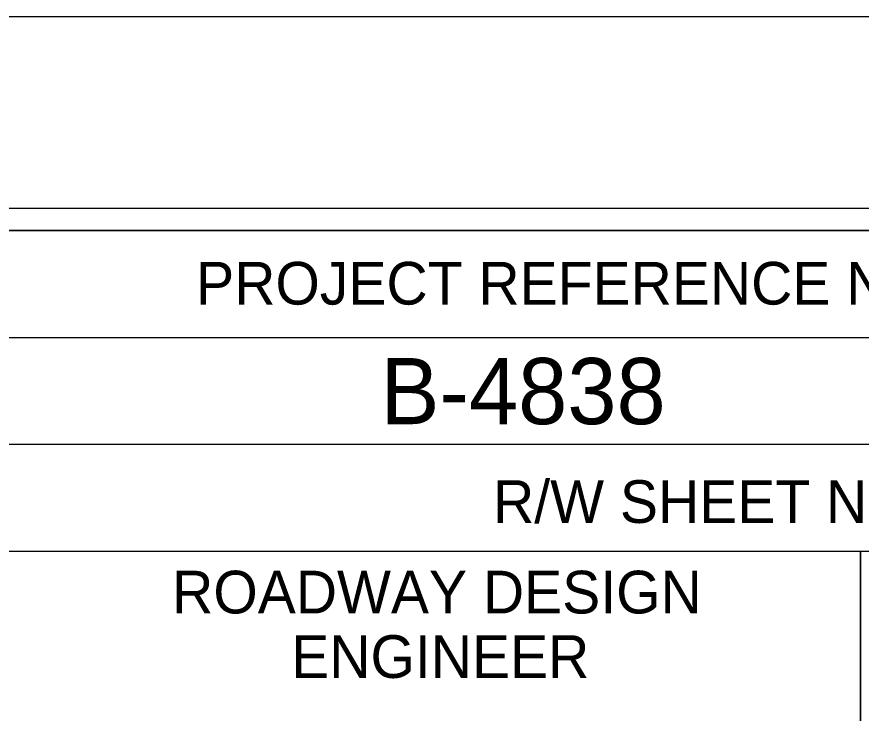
# Model space of a CAD drawing. Extents: x 270 to 1290, y -4845 to -4185.
# Drawn here: x 1150.7 to 1210, y -4233.7 to -4184.8 of the extents above; entities that cross this region are included whole.
import ezdxf

# ---------------------------------------------------------------- set-up
doc = ezdxf.new("R2010")
doc.units = 0
for name, color, linetype in [('Scratch_Level_1', 7, 'Continuous'), ('Sheet Border Standard 30in CELL', 7, 'Continuous'), ('Sheet Cutting Line CELL', 7, 'Continuous'), ('Sheet Data Field CELL', 7, 'Continuous'), ('Sheet Plot Border Inside CELL', 7, 'Continuous'), ('Sheet Plot Border Outside CELL', 7, 'Continuous'), ('Sheet Profile CELL', 7, 'Continuous')]:
    doc.layers.add(name, color=color, linetype=linetype)

msp = doc.modelspace()

# ---------------------------------------------------------------- linework, layer by layer
at = {"layer": 'Scratch_Level_1'}
msp.add_lwpolyline([(850, -4199.75), (1240, -4199.75), (1240, -4499.75), (850, -4499.75)], close=True, dxfattribs=at)
at = {"layer": 'Sheet Border Standard 30in CELL'}
for points in [[(1149.97, -4222.28), (1210, -4222.28), (1210, -4289.78), (1149.97, -4289.78)], [(1210, -4222.28), (1270.001, -4222.28), (1270.001, -4289.78), (1210, -4289.78)]]:
    msp.add_lwpolyline(points, close=True, dxfattribs=at)
at = {"layer": 'Sheet Cutting Line CELL'}
msp.add_line((1289.8, -4184.75), (269.8, -4184.75), dxfattribs=at)
at = {"layer": 'Sheet Plot Border Inside CELL'}
msp.add_lwpolyline([(277.6, -4831.28), (1277.5, -4831.28), (1277.5, -4198.22), (277.6, -4198.22)], close=True, dxfattribs=at)
at = {"layer": 'Sheet Plot Border Outside CELL'}
msp.add_lwpolyline([(269.8, -4844.75), (1289.8, -4844.75), (1289.8, -4184.75), (269.8, -4184.75)], close=True, dxfattribs=at)
at = {"layer": 'Sheet Profile CELL'}
msp.add_line((1149.97, -4207.28), (1270, -4207.28), dxfattribs=at)
for points in [[(1270, -4199.75), (370, -4199.75), (370, -4829.75), (1270, -4829.75)], [(1149.97, -4199.75), (1270, -4199.75), (1270, -4214.78), (1149.97, -4214.78)]]:
    msp.add_lwpolyline(points, close=True, dxfattribs=at)

# ---------------------------------------------------------------- texts
at = {"layer": 'Sheet Border Standard 30in CELL'}
for s, height, p in [('R/W SHEET NO.', 3.00007, (1184.17, -4220.3)), ('ROADWAY DESIGN', 3.00007, (1161.61, -4226.66)), ('ENGINEER', 3.0001, (1169.98, -4231.19))]:
    msp.add_text(s, height=height, rotation=0, dxfattribs=at).set_placement(p)
at = {"layer": 'Sheet Data Field CELL'}
msp.add_text('B-4838', height=4.6499, dxfattribs=at).set_placement((1176.253, -4213.363))
at = {"layer": 'Sheet Profile CELL'}
msp.add_text('PROJECT REFERENCE NO.', height=3.00006, dxfattribs=at).set_placement((1163.298, -4204.962))

doc.saveas('drawing.dxf')
